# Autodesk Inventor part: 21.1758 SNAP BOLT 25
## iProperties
Created: 2007-03
Part Number: 21.1758 SNAP BOLT 25
Document SubType Name: Modeling
Designer: Andy Moles
Material: Steel
Mass: 9.62317 g
Surface Area: 7.26478 cm^2
Volume: 1.22588 cm^3
Density: 7.85 g/cm^3
Author: Andy Moles
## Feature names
1. Extrusion1
2. Chamfer1
3. Extrusion2
4. Chamfer2
